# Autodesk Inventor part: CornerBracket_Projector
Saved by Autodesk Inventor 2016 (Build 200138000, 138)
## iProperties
Created: 2016-03
Part Number: CornerBracket_Projector
Material: Generic
Document SubType Name: Modeling
Designer: bongo_000
Density: 1 g/cm^3
Appearance: Default
Author: bongo_000
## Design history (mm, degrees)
feature "SOLID1"
body "Solid1"
